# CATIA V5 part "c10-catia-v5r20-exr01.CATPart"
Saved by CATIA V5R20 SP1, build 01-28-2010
Part number: Part2
Bounding box of the stored display mesh (mm): x -150 to 0, y -150 to 150, z 0 to 150
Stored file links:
  D:\v5_r20\psrt_files_downloaded\c10\c10-catia-v5r20-exr01.CATPart
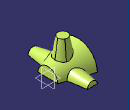
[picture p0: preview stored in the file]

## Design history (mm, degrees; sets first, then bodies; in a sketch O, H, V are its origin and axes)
Set1
  Plane1: type Offset, RefPlane yz-plane, Offset 150, reversed
  Plane2: type Offset, RefPlane zx-plane, Offset 150
  Plane3: type Offset, RefPlane zx-plane, Offset 150, reversed
  Plane4: type Offset, RefPlane xy-plane, Offset 150
  Sketch1 on yz-plane, origin (0, 0, 0), H (0, 1, 0), V (0, 0, 1)
    arc A1 centre (0, 0) radius 50 from (50, 0) to (-50, 0) ccw
    point P1 (-50, 0)
    point P2 (50, 0)
    radius A1 = 50
    coincidence: P1 H, P2 H
  Sketch2 on Plane1, origin (-150, 0, 0), H (0, 1, 0), V (0, 0, 1)
    arc A1 centre (0, 0) radius 100 from (100, 0) to (-100, 0) ccw
    point P1 (-100, 0)
    point P2 (100, 0)
    radius A1 = 100
    coincidence: P1 H, P2 H
  Blend1: StartLimit {blendlimit Curve Sketch1}, EndLimit {blendlimit Curve Sketch2}
  Sketch3 on Plane2, origin (0, 150, 0), H (-1, 0, 0), V (0, 0, 1)
    arc A1 centre (75, 0) radius 25 from (100, 0) to (50, 0) ccw
    point P1 (75, 0)
    point P2 (50, 0)
    point P3 (100, 0)
    radius A1 = 25
    distance P1 V = 75
    coincidence: P1 H, P2 H, P3 H
  Sketch4 on Plane3, origin (0, -150, 0), H (-1, 0, 0), V (0, 0, 1)
    arc A1 centre (75, 0) radius 25 from (100, 0) to (50, 0) ccw
    point P1 (75, 0)
    point P2 (50, 0)
    point P3 (100, 0)
    radius A1 = 25
    distance P1 V = 75
    coincidence: P1 H, P2 H, P3 H
  Sketch5 on zx-plane, origin (0, 0, 0), H (-1, 0, 0), V (0, 0, 1)
    arc A1 centre (75, 0) radius 50 from (125, 0) to (25, 0) ccw
    point P1 (75, 0)
    point P2 (25, 0)
    point P3 (125, 0)
    radius A1 = 50
    distance P1 V = 75
    coincidence: P1 H, P2 H, P3 H
  Blend2: StartLimit {blendlimit Curve Sketch3}, EndLimit {blendlimit Curve Sketch5}
  Blend3: StartLimit {blendlimit Curve Sketch4}, EndLimit {blendlimit Curve Sketch5}
  Sketch6 on Plane4, origin (0, 0, 150), H (1, 0, 0), V (0, 1, 0)
    circle A1 centre (-75, 0) radius 25
    point P1 (-75, 0)
    radius A1 = 25
    distance P1 V = 75
    coincidence: P1 H
  Sketch7 on xy-plane, origin (0, 0, 0), H (1, 0, 0), V (0, 1, 0)
    circle A1 centre (-75, 0) radius 50
    point P1 (-75, 0)
    radius A1 = 50
    distance P1 V = 75
    coincidence: P1 H
  Blend4: StartLimit {blendlimit Curve Sketch6, Point {extremum Reference Sketch6, Direction (1, 2, 3)}}, EndLimit {blendlimit Curve Sketch7, Point {extremum Reference Sketch7, Direction (1, 2, 3)}}
  Fill1: Boundary (Sketch1; {line type PtPt, FirstPoint vertex of Sketch1, SecondPoint vertex of Sketch1})
  Fill2: Boundary (Sketch2; {line type PtPt, FirstPoint vertex of Sketch2, SecondPoint vertex of Sketch2})
  Fill3: Boundary (Sketch4; {line type PtPt, FirstPoint vertex of Sketch4, SecondPoint vertex of Sketch4})
  Fill4: Boundary (Sketch3; {line type PtPt, FirstPoint vertex of Sketch3, SecondPoint vertex of Sketch3})
  Fill5: Boundary Sketch6
  Trim1: Element1 Blend4, Element2 Blend1
  Trim2: Element1 Blend2, Element2 Trim1
  Trim3: Element1 Blend3, Element2 Trim2
Body1 (main body)
  Sketch8 on zx-plane, origin (0, 0, 0), H (-1, 0, 0), V (0, 0, 1)
    arc A1 centre (0, 0) radius 50 from (50, 0) to (-50, 0) ccw
    point P1 (-50, 0)
    point P2 (50, 0)
    radius A1 = 50
    coincidence: P1 H, P2 H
